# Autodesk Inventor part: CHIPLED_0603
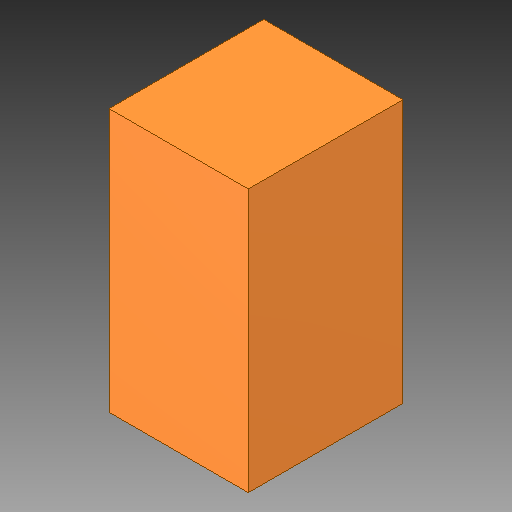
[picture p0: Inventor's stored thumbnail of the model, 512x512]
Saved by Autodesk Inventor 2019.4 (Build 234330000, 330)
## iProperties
Created: 2019-11
Part Number: CHIPLED_0603
Material: Generic
Document SubType Name: Modeling
Designer: Willist
Density: 1 g/cm^3
Appearance: CHIPLED_0603, CHIPLED_0603
Author: Willist
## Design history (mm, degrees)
sketch "CHIPLED_0603, CHIPLED_0603_26"
  geometry: L1 (-0.45, 0.851)-(0.45, 0.851); L2 (0.45, 0.851)-(0.45, -0.85); L3 (0.45, -0.85)-(-0.45, -0.85); L4 (-0.45, -0.85)-(-0.45, 0.851)
  constraints: 8 end point
extrude "Extrusion1" join sketch "CHIPLED_0603, CHIPLED_0603_26" distance "d0" = 1; taper "d1" = 0 deg
body "Solid1"
